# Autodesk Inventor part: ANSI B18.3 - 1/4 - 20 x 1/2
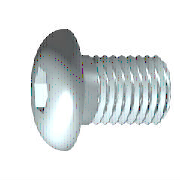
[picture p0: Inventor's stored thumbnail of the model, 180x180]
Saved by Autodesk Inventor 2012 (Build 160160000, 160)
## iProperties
Created: 2011-02
Part Number: ANSI B18.3 - 1/4 - 20 x 1/2
Material: Steel, Mild
Description: Hexagon Socket Button Head Cap Screw
Document SubType Name: Modeling
Standard: ANSI B18.3
Designer: Owner
Standard Revision: 2003
Standards Organization: ANSI
Language: en-US
Size Designation: 1/4 - 20 x 1/2
Categories: <MemberInstance><Categories><Category DisplayName="Fasteners" InternalName="e4da775c-781d-43d5-af7c-5136215cf5a6" Mnemonic="FSTN"><Category DisplayName="Bolts"
Density: 7.86 g/cm^3
Mass: 4.91915 g
Surface Area: 5.38681 cm^2
Volume: 0.625846 cm^3
IsCustomPart: 0
Author: Owner
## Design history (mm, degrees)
body "Solid1"
workplane "Work Plane1"
fillet "Fillet2" dims "d30" = 0.1 (= R)
revolve "Body" stored, may be unused: angle "d10" = 90 deg
sketch "Sketch2"
  geometry: L1 (0, -7.77)-(0, 7.77) reference; L2 (-7.77, 0)-(7.77, 0) reference; L3 (2.288, 0)-(1.144, -1.981); L4 (1.144, -1.981)-(-1.144, -1.981); L5 (-1.144, -1.981)-(-2.288, 0); L6 (-2.288, 0)-(-1.144, 1.981); L7 (-1.144, 1.981)-(1.144, 1.981); L8 (1.144, 1.981)-(2.288, 0); 2 further points
  constraints: 12 end point, 1 coincident, 1 horizontal alignment, 1 point on line, 12 other
extrude "Slot" join sketch "Sketch2" stored distance "d11" = 10; taper "d12" = 0 deg
fillet "Fillet1" dims "d17" = 2.9718 (= RR)
feature "Thread" dims "d13" = 10.1598 (= GEL), "d14" = 0
chamfer "Chamfer1" distance "d15" = 0.77902 (= -0.5 x SPD + 0.5 x GD); stored, may be unused: second distance "d16" = 0.77902 (= GUL), angle "d27" = 45 deg
sketch "Sketch1"
  geometry: L1 (0.178, 0)-(12.7, 0); L2 (12.7, 0)-(12.7, 3.175); L3 (12.7, 3.175)-(2.54, 3.175); L4 (2.54, 3.175)-(0, 3.175); L5 (0, 3.175)-(0, 3.175); L6 (0, 3.175)-(0, 5.55); L7 (0, 5.55)-(-3.353, 5.55); L8 (-3.353, 5.55)-(-3.353, 2.288); L9 (-3.353, 2.288)-(-1.143, 2.288); L10 (-1.143, 2.288)-(0.178, 0); L11 (-6.563, 0)-(15.911, 0) reference; L12 (0, -1.11)-(0, 6.66) reference; L13 (2.54, 3.175)-(0, 3.175)
  constraints: 22 end point, 6 parallel, 2 collinear, 2 perpendicular, 1 horizontal, 1 point on line
  dimensions: "d1" = 10.1598 distance from line of L3.end L2 (= GEL); "d2" = 2.5401 distance of L4.end L3.end (computed from GAL); "d3" = 3.3528 distance between parallel lines of L8 L6 (= KOH); "d4" = 2.2098 distance of L8.end L9.end (= INTI); "d5" = 60 deg angle of L10 L1; "d6" = 6.35 diameter of L3 L1 (= GD); "d7" = 6.35 diameter of L5 L1 (= BDM); "d8" = 4.57539 diameter of L9 L1 (= 1.1547 x SW); "d9" = 11.0998 diameter of L7 L1 (= KOD); "d26" = 12.7 distance between parallel lines of L12 L2 (= NLG)
other parameters: "GD" = 6.35 (= NND) [user parameter; used in 2 equation terms], "NLG" = 12.7 [user parameter; used in 1 equation term], "GEL" = 10.1598 [user parameter; used in 2 equation terms], "KOD" = 11.0998 [user parameter; used in 1 equation term], "KOH" = 3.3528 [user parameter; used in 1 equation term], "INTI" = 2.2098 [user parameter; used in 1 equation term], "GAL" = 2.54 [user parameter; used in 1 equation term], "GUL" = 0.77902 [user parameter; used in 1 equation term], "BDM" = 6.35 (= NND) [user parameter; used in 1 equation term], "SW" = 3.9624 [user parameter; used in 1 equation term], "RR" = 2.9718 [user parameter; used in 1 equation term], "SPD" = 4.79196 [user parameter; used in 2 equation terms], "d19" = 0, "d28" = 0, "d29" = 0, "R" = 0.1 [user parameter; used in 1 equation term], "TOA" = 30 deg [user parameter], "GD1" = 4.79196 (= SPD) [user parameter], "THREADDIA" = 6.35 [user parameter], "PTC" = 1.27 (computed from TPU) [user parameter], "KOH1" = 0.7874 [user parameter], "NND" = 6.35 [user parameter; used in 2 equation terms], "E0" = 4.57657 [user parameter]
